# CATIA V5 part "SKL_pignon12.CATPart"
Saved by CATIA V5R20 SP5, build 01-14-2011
Part number: SKL_pignon12
Publications: "Esquisse.1", "Point.1", "Droite.1"
Bounding box of the stored display mesh (mm): x -32 to 0, y 0 to 50.956, z -10 to 10
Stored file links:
  F:\Catia_finish\SKL_pignon12.CATPart
  F:\Catia_finish\ASS_SKL.CATProduct
  F:\Catia_finish\ASS_compresseur.CATProduct
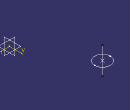
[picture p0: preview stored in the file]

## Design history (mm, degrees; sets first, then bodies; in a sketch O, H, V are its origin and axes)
External parameters (linked from other documents)
  External.rayon_pignon12 = 6 mm
Set1
  Point1: linked copy from another document
  Sketch1, origin (0, 0, 0), H (1, 0, 0), V (0, 1, 0), geometry linked from another document
  Plane1: linked copy from another document
Set2
  Point2: (0, 0, 0), relative to Point1
  Plane2: type Offset, RefPlane Plane1, Offset 0
  Line1: type Normal, RefPoint Point2, RefSkin Plane2, Start -10, End 10
Body1 (main body)
  Sketch2 on xy-plane, origin (0, 0, 0), H (1, 0, 0), V (0, 1, 0)
    circle A1 centre (-26, 45) radius 6
    point P1 (-26, 45)
    reference projected point E1 (-26, 45) from Point1
    radius A1 = 6 {= External.rayon_pignon12}
    coincidence: P1 E1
